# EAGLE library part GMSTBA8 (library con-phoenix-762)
PHOENIX
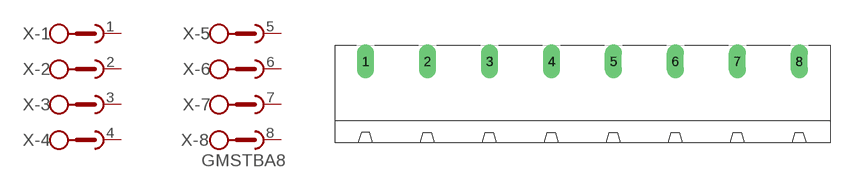
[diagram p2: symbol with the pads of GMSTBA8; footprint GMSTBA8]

Designator prefix X; gates -1=SKB -2=SKB -3=SKB -4=SKB -5=SKB -6=SKB -7=SKB -8=SKBV

## GMSTBA8 (MF: FARNELL; MPN: 1757307; OC_FARNELL: 3705225; OC_NEWARK: 71C4166)  [GMSTBA8]
1  -1:1  pas
2  -2:1  pas
3  -3:1  pas
4  -4:1  pas
5  -5:1  pas
6  -6:1  pas
7  -7:1  pas
8  -8:1  pas

## Footprint GMSTBA8 (pad centres in mm)
PHOENIX
drill 1.397 long: 1 -26.67,5.08; 2 -19.05,5.08; 3 -11.43,5.08; 4 -3.81,5.08; 5 3.81,5.08; 6 11.43,5.08; 7 19.05,5.08; 8 26.67,5.08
